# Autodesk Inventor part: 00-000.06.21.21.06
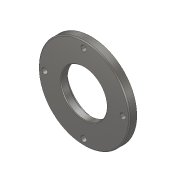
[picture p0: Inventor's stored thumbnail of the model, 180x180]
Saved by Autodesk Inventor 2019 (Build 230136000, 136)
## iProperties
Created: 2019-01
Part Number: 00-000.06.21.21.06
Material: Steel, Mild
Document SubType Name: Modeling
Designer: m.vorobev
Density: 7.85 g/cm^3
Appearance: Semi-Polished
Author: m.vorobev
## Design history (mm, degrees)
sketch "Sketch1"
  geometry: L1 (0, 0)-(7.413, 0); L2 (7.413, 0)-(7.413, -7.837); L3 (7.413, -7.837)-(0, -7.837); L4 (0, -7.837)-(0, 0); L5 (-35, 11.5)-(-70, 11.5); L6 (-70, 11.5)-(-70, 0); L7 (-70, 0)-(-35, 0); L8 (-35, 0)-(-35, 11.5); L9 (-50, 0)-(-45, 0); L10 (-45, 0)-(-45, -7.5); L11 (-45, -7.5)-(-50, -7.5); L12 (-50, -7.5)-(-50, 0); L13 (-45, 0)-(-35, 0); L14 (-35, 0)-(-35, 0.5); L15 (-35, 0.5)-(-45, 0.5); L16 (-45, 0.5)-(-45, 0); 1 further point
  constraints: 32 end point, 8 parallel, 4 horizontal, 4 perpendicular, 2 point on line, 1 horizontal alignment, 1 midpoint
  dimensions: "d0" = 19 distance between parallel lines of L5 L11; "d1" = 140 diameter of L6 L4; "d2" = 100 diameter of L12 L4; "d3" = 90 diameter of L10 L4; "d4" = 7.5 distance of L11.end L9.start; "d5" = 0.5 distance of L15.end L9.end; "Ukn" = 70 diameter of L8 L4
revolve "Revolution1" sketch "Sketch1" stored, may be unused: angle "d7" = 90 deg
chamfer "Chamfer1" distance "d8" = 1; stored, may be unused: second distance "d9" = 2, angle "d10" = 45 deg
fillet "Fillet1" dims "d11" = 2
chamfer "Chamfer2" distance "d12" = 1.5; stored, may be unused: second distance "d13" = 2, angle "d14" = 45 deg
sketch "Sketch2"
  geometry: L1 (0, 0)-(0, -60)
  constraints: 2 end point, 1 vertical
  dimensions: "d15" = 60 distance of L1.start L1.end
hole "Hole1" sketch "Sketch2" at (0, -60) diameter "d16" = 9; stored, may be unused: countersink angle "d20" = 90 deg, drill point angle "d22" = 118 deg; dims "d17" = 17, "d18" = 12, "d19" = 2, "d21" = 24
pattern_circular "Circular Pattern1" dims angle "d24" = 360 deg
body "Solid1"
